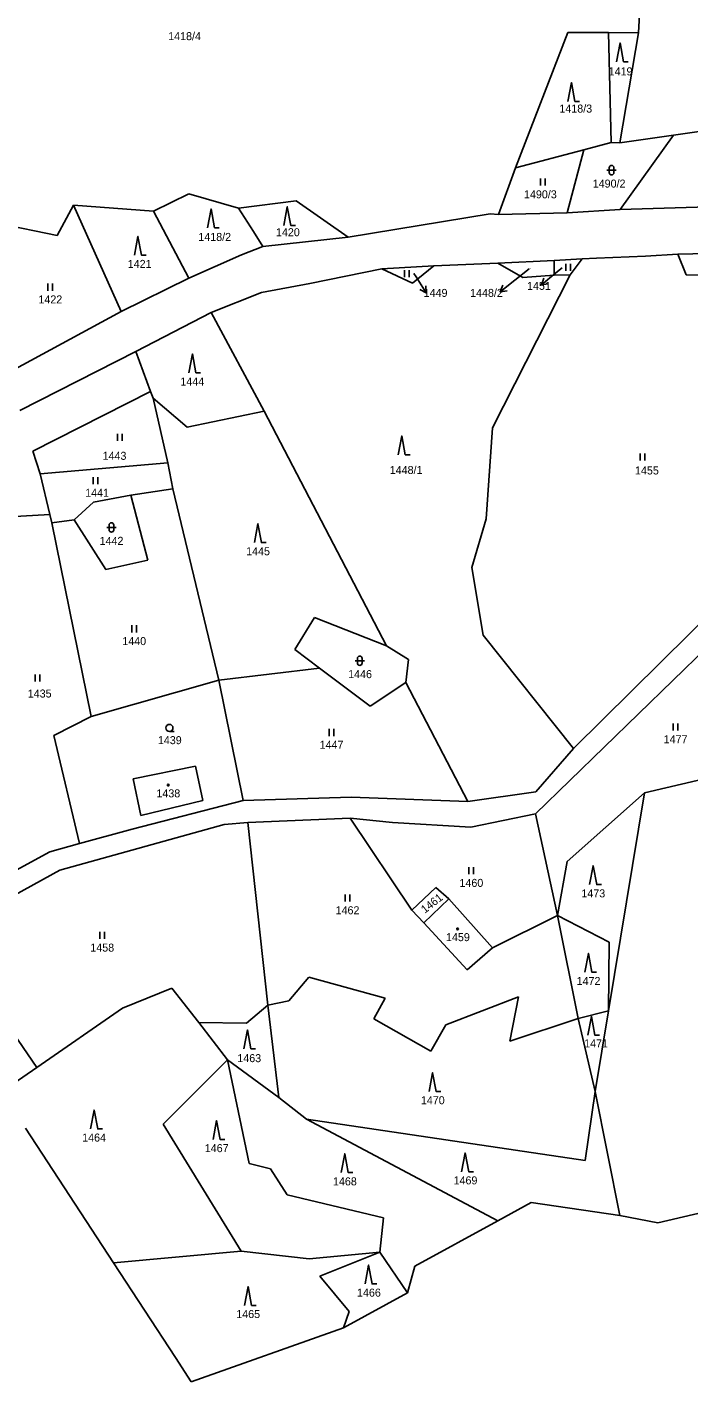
# Model space of a CAD drawing. Extents: x -670359 to -660124, y -978807 to -970072.
# Drawn here: x -669263 to -669122.6, y -978803.7 to -978516 of the extents above; entities that cross this region are included whole.
import ezdxf

# ---------------------------------------------------------------- set-up
doc = ezdxf.new("R2010")
doc.units = 0
for name, color, linetype in [('Hranice kat_území', 7, 'Continuous'), ('Hranice parcel', 7, 'Continuous'), ('Parcelní čísla', 7, 'Continuous'), ('Vnitřní kresba', 7, 'Continuous'), ('Značky budov', 7, 'Continuous'), ('Značky kultur', 7, 'Continuous')]:
    doc.layers.add(name, color=color, linetype=linetype)

msp = doc.modelspace()

# ---------------------------------------------------------------- linework, layer by layer
at = {"layer": 'Hranice kat_území'}
for points in [[(-669263.36, -978749.8), (-669244.69, -978778.42)], [(-669163.16, -978769.47), (-669156.07, -978765.63)], [(-669156.07, -978765.63), (-669137.21, -978768.39)], [(-669129.14, -978769.92), (-669116.14, -978766.86)], [(-669180.71, -978779.12), (-669163.16, -978769.47)], [(-669137.21, -978768.39), (-669129.14, -978769.92)], [(-669244.69, -978778.42), (-669231.58, -978798.52)], [(-669182.29, -978784.78), (-669180.71, -978779.12)], [(-669195.9, -978792.23), (-669182.29, -978784.78)], [(-669228.19, -978803.71), (-669195.9, -978792.23)], [(-669231.58, -978798.52), (-669228.19, -978803.71)]]:
    msp.add_lwpolyline(points, dxfattribs=at)
at = {"layer": 'Hranice parcel'}
for points in [[(-669132.89, -978510.73), (-669133.28, -978517.2)], [(-669148.3, -978517.08), (-669159.36, -978545.88)], [(-669139.6, -978517.13), (-669148.3, -978517.08)], [(-669133.28, -978517.2), (-669139.6, -978517.13)], [(-669139.6, -978517.13), (-669139.05, -978540.5)], [(-669133.28, -978517.2), (-669137.21, -978540.52)], [(-669125.82, -978538.9), (-669111.55, -978536.87)], [(-669137.21, -978540.52), (-669125.82, -978538.9)], [(-669125.82, -978538.9), (-669137.18, -978554.7)], [(-669144.86, -978542.03), (-669159.36, -978545.88)], [(-669144.86, -978542.03), (-669148.42, -978555.4)], [(-669139.05, -978540.5), (-669144.86, -978542.03)], [(-669137.21, -978540.52), (-669139.05, -978540.5)], [(-669159.36, -978545.88), (-669162.97, -978555.76)], [(-669236.22, -978555.04), (-669228.74, -978551.39)], [(-669228.74, -978551.39), (-669218.2, -978554.44)], [(-669253.18, -978553.82), (-669256.69, -978560.26)], [(-669236.22, -978555.04), (-669253.18, -978553.82)], [(-669253.18, -978553.82), (-669243.09, -978576.4)], [(-669205.94, -978552.89), (-669218.2, -978554.44)], [(-669218.2, -978554.44), (-669215, -978559.4)], [(-669194.89, -978560.61), (-669205.94, -978552.89)], [(-669099.72, -978553.56), (-669137.18, -978554.7)], [(-669228.69, -978569.28), (-669236.22, -978555.04)], [(-669164.76, -978555.64), (-669194.89, -978560.61)], [(-669162.97, -978555.76), (-669164.76, -978555.64)], [(-669148.42, -978555.4), (-669162.97, -978555.76)], [(-669137.18, -978554.7), (-669148.42, -978555.4)], [(-669256.69, -978560.26), (-669269.15, -978557.65)], [(-669215, -978559.4), (-669213.01, -978562.57)], [(-669213.01, -978562.57), (-669217.51, -978564.36)], [(-669194.89, -978560.61), (-669213.01, -978562.57)], [(-669217.51, -978564.36), (-669228.69, -978569.28)], [(-669176.71, -978566.64), (-669163.15, -978566.07)], [(-669151.16, -978565.56), (-669163.15, -978566.07)], [(-669163.15, -978566.07), (-669157.81, -978569.14)], [(-669151.16, -978565.56), (-669151.19, -978568.68)], [(-669145.19, -978565.2), (-669151.16, -978565.56)], [(-669145.19, -978565.2), (-669147.75, -978568.56)], [(-669142.19, -978565.02), (-669145.19, -978565.2)], [(-669131.78, -978564.65), (-669142.19, -978565.02)], [(-669124.89, -978564.16), (-669131.78, -978564.65)], [(-669115.28, -978563.95), (-669124.89, -978564.16)], [(-669187.76, -978567.32), (-669203, -978570.44)], [(-669176.71, -978566.64), (-669187.76, -978567.32)], [(-669187.76, -978567.32), (-669181.23, -978570.35)], [(-669181.23, -978570.35), (-669176.71, -978566.64)], [(-669147.75, -978568.56), (-669164.26, -978601.09)], [(-669157.81, -978569.14), (-669151.19, -978568.68)], [(-669151.19, -978568.68), (-669147.75, -978568.56)], [(-669228.69, -978569.28), (-669243.09, -978576.4)], [(-669203, -978570.44), (-669213.27, -978572.33)], [(-669213.27, -978572.33), (-669223.96, -978576.61)], [(-669243.09, -978576.4), (-669266.44, -978589.03)], [(-669223.96, -978576.61), (-669239.98, -978584.84)], [(-669223.96, -978576.61), (-669212.73, -978597.53)], [(-669239.98, -978584.84), (-669264.6, -978597.37)], [(-669239.98, -978584.84), (-669236.86, -978593.34)], [(-669261.81, -978606.04), (-669236.86, -978593.34)], [(-669236.86, -978593.34), (-669236.32, -978594.79)], [(-669236.32, -978594.79), (-669233.18, -978608.51)], [(-669229.1, -978600.95), (-669236.32, -978594.79)], [(-669212.73, -978597.53), (-669229.1, -978600.95)], [(-669212.73, -978597.53), (-669186.76, -978647.4)], [(-669164.26, -978601.09), (-669165.59, -978620.43)], [(-669261.81, -978606.04), (-669260.26, -978610.85)], [(-669233.18, -978608.51), (-669260.26, -978610.85)], [(-669233.18, -978608.51), (-669232.12, -978614.04)], [(-669085.33, -978608.18), (-669147.05, -978669.18)], [(-669260.26, -978610.85), (-669258.19, -978619.51)], [(-669232.12, -978614.04), (-669241.02, -978615.38)], [(-669232.12, -978614.04), (-669222.38, -978654.69)], [(-669248.96, -978616.89), (-669253.08, -978620.61)], [(-669241.02, -978615.38), (-669248.96, -978616.89)], [(-669241.02, -978615.38), (-669237.4, -978629.18)], [(-669258.19, -978619.51), (-669289.11, -978621.26)], [(-669258.19, -978619.51), (-669257.81, -978621.28)], [(-669253.08, -978620.61), (-669257.81, -978621.28)], [(-669246.31, -978631.16), (-669253.08, -978620.61)], [(-669165.59, -978620.43), (-669168.66, -978630.72)], [(-669257.81, -978621.28), (-669249.44, -978662.4)], [(-669237.4, -978629.18), (-669246.31, -978631.16)], [(-669168.66, -978630.72), (-669166.25, -978645.14)], [(-669111.37, -978640.61), (-669155.12, -978683.09)], [(-669202.07, -978641.39), (-669206.22, -978648.15)], [(-669186.76, -978647.4), (-669202.07, -978641.39)], [(-669166.25, -978645.14), (-669147.05, -978669.18)], [(-669206.22, -978648.15), (-669200.98, -978652.12)], [(-669186.76, -978647.4), (-669182.07, -978650.25)], [(-669200.98, -978652.12), (-669222.38, -978654.69)], [(-669190.26, -978660.16), (-669200.98, -978652.12)], [(-669182.07, -978650.25), (-669182.68, -978655.2)], [(-669222.38, -978654.69), (-669249.44, -978662.4)], [(-669222.38, -978654.69), (-669217.21, -978680.26)], [(-669182.68, -978655.2), (-669190.26, -978660.16)], [(-669182.68, -978655.2), (-669169.5, -978680.46)], [(-669249.44, -978662.4), (-669257.4, -978666.4)], [(-669257.4, -978666.4), (-669251.96, -978689.39)], [(-669147.05, -978669.18), (-669155.07, -978678.38)], [(-669094.87, -978669.91), (-669132.02, -978678.62)], [(-669240.53, -978675.61), (-669227.3, -978672.96)], [(-669227.3, -978672.96), (-669225.77, -978680.25)], [(-669238.94, -978683.39), (-669240.53, -978675.61)], [(-669217.21, -978680.26), (-669240.73, -978686.33)], [(-669225.77, -978680.25), (-669238.94, -978683.39)], [(-669194.23, -978679.55), (-669217.21, -978680.26)], [(-669169.5, -978680.46), (-669194.23, -978679.55)], [(-669155.07, -978678.38), (-669169.5, -978680.46)], [(-669132.02, -978678.62), (-669148.42, -978693.16)], [(-669132.02, -978678.62), (-669139.63, -978724.93)], [(-669194.44, -978683.95), (-669216.22, -978684.91)], [(-669185.48, -978684.93), (-669194.44, -978683.95)], [(-669194.44, -978683.95), (-669181.35, -978703.53)], [(-669155.12, -978683.09), (-669168.84, -978685.91)], [(-669155.12, -978683.09), (-669150.47, -978704.66)], [(-669221.19, -978685.34), (-669256.11, -978695.04)], [(-669240.73, -978686.33), (-669251.96, -978689.39)], [(-669216.22, -978684.91), (-669221.19, -978685.34)], [(-669216.22, -978684.91), (-669211.98, -978723.67)], [(-669168.84, -978685.91), (-669185.48, -978684.93)], [(-669251.96, -978689.39), (-669258.23, -978691.1)], [(-669258.23, -978691.1), (-669274.17, -978699.8)], [(-669256.11, -978695.04), (-669282.2, -978709.4)], [(-669148.42, -978693.16), (-669150.47, -978704.66)], [(-669181.35, -978703.53), (-669176.26, -978698.7)], [(-669173.56, -978701.13), (-669178.82, -978706.19)], [(-669176.26, -978698.7), (-669173.56, -978701.13)], [(-669173.56, -978701.13), (-669164.23, -978711.55)], [(-669181.35, -978703.53), (-669178.82, -978706.19)], [(-669178.82, -978706.19), (-669169.64, -978716.21)], [(-669164.23, -978711.55), (-669150.47, -978704.66)], [(-669150.47, -978704.66), (-669146.06, -978726.54)], [(-669139.48, -978710.3), (-669150.47, -978704.66)], [(-669169.64, -978716.21), (-669164.23, -978711.55)], [(-669139.63, -978724.93), (-669139.48, -978710.3)], [(-669207.49, -978722.76), (-669203.28, -978717.77)], [(-669203.28, -978717.77), (-669187.07, -978722.18)], [(-669232.36, -978720.09), (-669242.81, -978724.3)], [(-669226.59, -978727.35), (-669232.36, -978720.09)], [(-669270.97, -978722.4), (-669260.95, -978736.9)], [(-669242.81, -978724.3), (-669260.95, -978736.9)], [(-669211.98, -978723.67), (-669216.51, -978727.54)], [(-669211.98, -978723.67), (-669207.49, -978722.76)], [(-669209.63, -978743.29), (-669211.98, -978723.67)], [(-669187.07, -978722.18), (-669189.44, -978726.63)], [(-669174.17, -978727.84), (-669158.73, -978721.93)], [(-669158.73, -978721.93), (-669160.6, -978731.35)], [(-669189.44, -978726.63), (-669177.35, -978733.48)], [(-669160.6, -978731.35), (-669146.06, -978726.54)], [(-669139.63, -978724.93), (-669146.06, -978726.54)], [(-669146.06, -978726.54), (-669142.46, -978742.02)], [(-669139.63, -978724.93), (-669142.46, -978742.02)], [(-669216.51, -978727.54), (-669226.59, -978727.35)], [(-669226.59, -978727.35), (-669220.51, -978735.34)], [(-669177.35, -978733.48), (-669174.17, -978727.84)], [(-669220.51, -978735.34), (-669234.18, -978748.95)], [(-669220.51, -978735.34), (-669215.94, -978757.3)], [(-669220.51, -978735.34), (-669209.63, -978743.29)], [(-669260.95, -978736.9), (-669267.86, -978741.7)], [(-669209.63, -978743.29), (-669203.76, -978747.92)], [(-669144.61, -978756.71), (-669142.46, -978742.02)], [(-669142.46, -978742.02), (-669137.21, -978768.39)], [(-669234.18, -978748.95), (-669217.58, -978775.92)], [(-669203.76, -978747.92), (-669163.16, -978769.47)], [(-669203.76, -978747.92), (-669144.61, -978756.71)], [(-669215.94, -978757.3), (-669211.39, -978758.47)], [(-669211.39, -978758.47), (-669207.85, -978763.95)], [(-669207.85, -978763.95), (-669187.41, -978768.89)], [(-669187.41, -978768.89), (-669188.2, -978776.16)], [(-669217.58, -978775.92), (-669244.69, -978778.42)], [(-669217.58, -978775.92), (-669203.19, -978777.6)], [(-669203.19, -978777.6), (-669188.2, -978776.16)], [(-669188.2, -978776.16), (-669200.91, -978781.22)], [(-669188.2, -978776.16), (-669182.29, -978784.78)], [(-669200.91, -978781.22), (-669194.66, -978788.73)], [(-669194.66, -978788.73), (-669195.9, -978792.23)]]:
    msp.add_lwpolyline(points, dxfattribs=at)
at = {"layer": 'Parcelní čísla'}
for p, q in [((-669180.94, -978568.31), (-669180.48, -978569.04)), ((-669156.49, -978567.33), (-669159.51, -978569.71)), ((-669149.48, -978567.11), (-669150.79, -978568.18)), ((-669178.4, -978570.92), (-669178.34, -978572.42)), ((-669152.41, -978570.47), (-669153.89, -978570.7)), ((-669161.16, -978571.97), (-669162.65, -978572.19))]:
    msp.add_line(p, q, dxfattribs=at)
for points in [[(-669150.79, -978568.18), (-669153.89, -978570.7), (-669153.36, -978569.3)], [(-669180.48, -978569.04), (-669178.34, -978572.42), (-669179.67, -978571.72)], [(-669159.51, -978569.71), (-669162.65, -978572.19), (-669162.09, -978570.79)]]:
    msp.add_lwpolyline(points, dxfattribs=at)
at = {"layer": 'Vnitřní kresba'}
for points in [[(-669124.89, -978564.16), (-669123.18, -978568.58)], [(-669123.18, -978568.58), (-669117.25, -978568.65)]]:
    msp.add_lwpolyline(points, dxfattribs=at)
at = {"layer": 'Značky budov'}
for centre in [(-669233.1, -978676.96), (-669171.67, -978707.5)]:
    msp.add_circle(centre, 0.175, dxfattribs=at)
at = {"layer": 'Značky kultur'}
for p, q in [((-669139.48, -978545.85), (-669139.48, -978546.85)), ((-669138.48, -978545.85), (-669138.48, -978546.85)), ((-669154.07, -978548.13), (-669154.07, -978549.63)), ((-669153.07, -978549.63), (-669153.07, -978548.13)), ((-669139.98, -978546.35), (-669137.98, -978546.35)), ((-669182.96, -978567.6), (-669182.96, -978569.1)), ((-669181.96, -978569.1), (-669181.96, -978567.6)), ((-669148.71, -978566.23), (-669148.71, -978567.73)), ((-669147.71, -978567.73), (-669147.71, -978566.23)), ((-669258.65, -978570.45), (-669258.65, -978571.95)), ((-669257.65, -978571.95), (-669257.65, -978570.45)), ((-669243.85, -978602.37), (-669243.85, -978603.87)), ((-669242.85, -978603.87), (-669242.85, -978602.37)), ((-669132.94, -978606.55), (-669132.94, -978608.05)), ((-669131.94, -978608.05), (-669131.94, -978606.55)), ((-669249.04, -978611.52), (-669249.04, -978613.02)), ((-669248.04, -978613.02), (-669248.04, -978611.52)), ((-669246.16, -978622.23), (-669244.16, -978622.23)), ((-669245.66, -978621.73), (-669245.66, -978622.73)), ((-669244.66, -978621.73), (-669244.66, -978622.73)), ((-669240.84, -978643.02), (-669240.84, -978644.52)), ((-669239.84, -978644.52), (-669239.84, -978643.02)), ((-669193.44, -978650.54), (-669191.44, -978650.54)), ((-669192.94, -978650.04), (-669192.94, -978651.04)), ((-669191.94, -978650.04), (-669191.94, -978651.04)), ((-669261.32, -978653.48), (-669261.32, -978654.98)), ((-669260.32, -978654.98), (-669260.32, -978653.48)), ((-669125.92, -978663.86), (-669125.92, -978665.36)), ((-669124.92, -978665.36), (-669124.92, -978663.86)), ((-669232.83, -978665.56), (-669231.83, -978665.56)), ((-669198.96, -978665.04), (-669198.96, -978666.54)), ((-669197.96, -978666.54), (-669197.96, -978665.04)), ((-669169.27, -978694.38), (-669169.27, -978695.88)), ((-669168.27, -978695.88), (-669168.27, -978694.38)), ((-669195.56, -978700.19), (-669195.56, -978701.69)), ((-669194.56, -978701.69), (-669194.56, -978700.19)), ((-669247.63, -978708.12), (-669247.63, -978709.62)), ((-669246.63, -978709.62), (-669246.63, -978708.12))]:
    msp.add_line(p, q, dxfattribs=at)
for points in [[(-669137.94, -978523.34), (-669137.19, -978519.34), (-669136.44, -978523.34), (-669135.44, -978523.34)], [(-669148.26, -978531.76), (-669147.51, -978527.76), (-669146.76, -978531.76), (-669145.76, -978531.76)], [(-669208.56, -978558.13), (-669207.81, -978554.13), (-669207.06, -978558.13), (-669206.06, -978558.13)], [(-669224.76, -978558.58), (-669224.01, -978554.58), (-669223.26, -978558.58), (-669222.26, -978558.58)], [(-669240.26, -978564.41), (-669239.51, -978560.41), (-669238.76, -978564.41), (-669237.76, -978564.41)], [(-669228.72, -978589.39), (-669227.97, -978585.39), (-669227.22, -978589.39), (-669226.22, -978589.39)], [(-669184.27, -978606.78), (-669183.52, -978602.78), (-669182.77, -978606.78), (-669181.77, -978606.78)], [(-669214.8, -978625.44), (-669214.05, -978621.44), (-669213.3, -978625.44), (-669212.3, -978625.44)], [(-669143.64, -978698.1), (-669142.89, -978694.1), (-669142.14, -978698.1), (-669141.14, -978698.1)], [(-669144.65, -978716.71), (-669143.9, -978712.71), (-669143.15, -978716.71), (-669142.15, -978716.71)], [(-669144.01, -978730.08), (-669143.26, -978726.08), (-669142.51, -978730.08), (-669141.51, -978730.08)], [(-669217.04, -978732.96), (-669216.29, -978728.96), (-669215.54, -978732.96), (-669214.54, -978732.96)], [(-669177.71, -978742.04), (-669176.96, -978738.04), (-669176.21, -978742.04), (-669175.21, -978742.04)], [(-669249.57, -978749.97), (-669248.82, -978745.97), (-669248.07, -978749.97), (-669247.07, -978749.97)], [(-669223.58, -978752.21), (-669222.83, -978748.21), (-669222.08, -978752.21), (-669221.08, -978752.21)], [(-669196.37, -978759.27), (-669195.62, -978755.27), (-669194.87, -978759.27), (-669193.87, -978759.27)], [(-669170.81, -978759.06), (-669170.06, -978755.06), (-669169.31, -978759.06), (-669168.31, -978759.06)], [(-669191.31, -978782.9), (-669190.56, -978778.9), (-669189.81, -978782.9), (-669188.81, -978782.9)], [(-669216.9, -978787.45), (-669216.15, -978783.45), (-669215.4, -978787.45), (-669214.4, -978787.45)]]:
    msp.add_lwpolyline(points, dxfattribs=at)
for centre, radius in [((-669232.83, -978664.81), 0.75), ((-669233.1, -978676.96), 0.175), ((-669171.67, -978707.5), 0.175)]:
    msp.add_circle(centre, radius, dxfattribs=at)
for centre, start, end in [((-669138.98, -978545.85), 0, 180), ((-669138.98, -978546.85), 180, 0), ((-669245.16, -978621.73), 0, 180), ((-669245.16, -978622.73), 180, 0), ((-669192.44, -978650.04), 0, 180), ((-669192.44, -978651.04), 180, 0)]:
    msp.add_arc(centre, 0.5, start, end, dxfattribs=at)

# ---------------------------------------------------------------- texts
at = {"layer": 'Parcelní čísla'}
for s, height, p in [('1418/4', 1.7, (-669233.1, -978518.74)), ('1419', 1.7, (-669139.6, -978526.22)), ('1418/3', 1.7, (-669150.06, -978534.12)), ('1490/2', 1.7, (-669142.98, -978550.05)), ('1490/3', 1.7, (-669157.57, -978552.33)), ('1418/2', 1.7, (-669226.7, -978561.38)), ('1420', 1.7, (-669210.22, -978560.38)), ('1421', 1.7, (-669241.69, -978567.11)), ('1449', 0.1, (-669180.94, -978568.31)), ('1448/2', 0.1, (-669156.49, -978567.33)), ('1451', 0.1, (-669149.48, -978567.11)), ('1449', 1.7, (-669178.87, -978573.27)), ('1448/2', 1.7, (-669169.01, -978573.27)), ('1451', 1.7, (-669156.92, -978571.77)), ('1422', 1.7, (-669260.65, -978574.65)), ('1444', 1.7, (-669230.51, -978592.09)), ('1443', 1.7, (-669247.03, -978607.87)), ('1448/1', 1.7, (-669186.07, -978610.88)), ('1455', 1.7, (-669134.01, -978610.98)), ('1441', 1.7, (-669250.72, -978615.72)), ('1442', 1.7, (-669247.66, -978625.93)), ('1445', 1.7, (-669216.55, -978628.14)), ('1440', 1.7, (-669242.84, -978647.22)), ('1446', 1.7, (-669194.9, -978654.24)), ('1435', 1.7, (-669262.91, -978658.36)), ('1439', 1.7, (-669235.29, -978668.26)), ('1477', 1.7, (-669127.92, -978668.06)), ('1447', 1.7, (-669200.96, -978669.24)), ('1438', 1.7, (-669235.6, -978679.56)), ('1460', 1.7, (-669171.27, -978698.58)), ('1473', 1.7, (-669145.39, -978700.8)), ('1462', 1.7, (-669197.56, -978704.39)), ('1459', 1.7, (-669174.13, -978710.1)), ('1458', 1.7, (-669249.63, -978712.32)), ('1472', 1.7, (-669146.4, -978719.41)), ('1471', 1.7, (-669144.8, -978732.67)), ('1463', 1.7, (-669218.42, -978735.8)), ('1470', 1.7, (-669179.46, -978744.74)), ('1464', 1.7, (-669251.36, -978752.67)), ('1467', 1.7, (-669225.33, -978754.91)), ('1468', 1.7, (-669198.12, -978761.97)), ('1469', 1.7, (-669172.52, -978761.76)), ('1466', 1.7, (-669193.02, -978785.6)), ('1465', 1.7, (-669218.65, -978790.15))]:
    msp.add_text(s, height=height, dxfattribs=at).set_placement(p)
msp.add_text('1461', height=1.7, rotation=38.1572, dxfattribs=at).set_placement((-669178.61, -978704.28))

doc.saveas('drawing.dxf')
